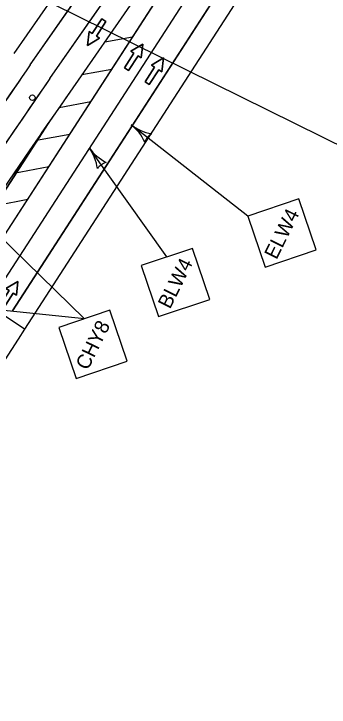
# Model space of a CAD drawing. Extents: x 14097936 to 14128734, y 8632000 to 8683104.
# Drawn here: x 14119195.8 to 14119353.7, y 8668694.3 to 8669041.8 of the extents above; entities that cross this region are included whole.
import ezdxf

# ---------------------------------------------------------------- set-up
doc = ezdxf.new("R2010")
doc.units = 0
for name, color, linetype in [('Cell', 7, 'Continuous'), ('dsn_stg_shd_prev', 7, 'Continuous'), ('dsnNonPlotable', 7, 'Continuous'), ('dsnPaintExistingChannelizingLaneWhite', 7, 'Continuous'), ('dsnPaintExistingDoubleCenterYellow', 7, 'Continuous'), ('dsnPaintPlaceBrokenLaneWhite', 7, 'Continuous'), ('dsnPaintPlaceChannelizingLaneWhite', 7, 'Continuous'), ('dsnPaintPlaceChannelizingLaneYellow', 7, 'Continuous'), ('dsnPaintPlaceEdgeLineRightWhite', 7, 'Continuous'), ('dsnPavementRmvl', 7, 'Continuous'), ('dsnShadingPaved', 7, 'Continuous'), ('dsnStdLabel', 7, 'Continuous'), ('dsnStgShadingPropPav', 7, 'Continuous'), ('Level 2', 7, 'Continuous'), ('Level 5', 7, 'Continuous')]:
    doc.layers.add(name, color=color, linetype=linetype)

msp = doc.modelspace()

# ---------------------------------------------------------------- linework, layer by layer
at = {"layer": 'Cell'}
msp.add_circle((14119205.09, 8668999.85), 1.37, dxfattribs=at)
at = {"layer": 'dsn_stg_shd_prev'}
for p, q in [((14119162.43, 8668908.54), (14119212.98, 8668986.84)), ((14119212.98, 8668986.84), (14119164.55, 8668911.89))]:
    msp.add_line(p, q, dxfattribs=at)
msp.add_arc((14121592.11, 8667345.68), 2842.95, 147.24613, 151.16499, dxfattribs=at)
at = {"layer": 'dsnNonPlotable'}
msp.add_lwpolyline([(14118047.21, 8667875.87), (14118741.94, 8669281.01), (14119647.32, 8668833.36), (14118952.59, 8667428.23)], close=True, dxfattribs=at)
at = {"layer": 'dsnPaintExistingChannelizingLaneWhite'}
for radius, end in [(1512, 159.62671), (1488, 158.15787)]:
    msp.add_arc((14120503.02, 8668359.24), radius, 147.24256, end, dxfattribs=at)
at = {"layer": 'dsnPaintExistingDoubleCenterYellow'}
msp.add_arc((14120503.02, 8668359.24), 1500, 147.24256, 159.62671, dxfattribs=at)
at = {"layer": 'dsnPaintPlaceBrokenLaneWhite'}
msp.add_line((14119527.44, 8669429.79), (14119185.09, 8668899.43), dxfattribs=at)
at = {"layer": 'dsnPaintPlaceChannelizingLaneWhite'}
msp.add_line((14119213.91, 8669009.38), (14119238.52, 8669044.85), dxfattribs=at)
msp.add_arc((14123732.96, 8665874.38), 5500, 145.2497, 146.42378, dxfattribs=at)
at = {"layer": 'dsnPaintPlaceChannelizingLaneYellow'}
for p, q in [((14119175.01, 8668905.94), (14119397.41, 8669250.48)), ((14119334.31, 8669161.88), (14119223.77, 8669002.54)), ((14119241.31, 8669027.81), (14119255.31, 8669030.35)), ((14119229.91, 8669011.38), (14119244.81, 8669014.08)), ((14119218.51, 8668994.94), (14119234.32, 8668997.83)), ((14119207.17, 8668978.47), (14119223.83, 8668981.58)), ((14119195.89, 8668961.96), (14119213.3, 8668965.27)), ((14119184.67, 8668945.4), (14119202.74, 8668948.91))]:
    msp.add_line(p, q, dxfattribs=at)
msp.add_arc((14123732.96, 8665874.38), 5488, 145.2497, 146.41498, dxfattribs=at)
at = {"layer": 'dsnPaintPlaceEdgeLineRightWhite'}
msp.add_line((14119195.17, 8668892.92), (14119537.53, 8669423.29), dxfattribs=at)
at = {"layer": 'dsnPavementRmvl'}
for radius, end in [(1512, 159.62671), (1488, 158.15787)]:
    msp.add_arc((14120503.02, 8668359.24), radius, 147.24256, end, dxfattribs=at)
at = {"layer": 'dsnShadingPaved'}
for p, q in [((14119175.01, 8668905.94), (14119517.35, 8669436.29)), ((14119213.91, 8669009.38), (14119324.45, 8669168.72)), ((14119334.31, 8669161.88), (14119223.77, 8669002.54))]:
    msp.add_line(p, q, dxfattribs=at)
msp.add_lwpolyline([(14119537.53, 8669423.29), (14119537.53, 8669423.29), (14119195.17, 8668892.92)], dxfattribs=at)
for radius in [5500, 5488]:
    msp.add_arc((14123732.96, 8665874.38), radius, 145.2497, 157.1633, dxfattribs=at)
at = {"layer": 'dsnStdLabel'}
for p, q in [((14119312.96, 8668940.41), (14119254.54, 8668986.28)), ((14119272.43, 8668919.95), (14119233.61, 8668974.6)), ((14119231.14, 8668888.99), (14119180.2, 8668938.78)), ((14119231.14, 8668888.99), (14119168.3, 8668895.51))]:
    msp.add_line(p, q, dxfattribs=at)
for points in [[(14119321.61, 8668914.84), (14119347.19, 8668923.49), (14119338.54, 8668949.06), (14119312.96, 8668940.41)], [(14119268.29, 8668890.05), (14119293.87, 8668898.7), (14119285.21, 8668924.28), (14119259.64, 8668915.63)], [(14119227, 8668859.08), (14119252.58, 8668867.74), (14119243.93, 8668893.31), (14119218.35, 8668884.66)]]:
    msp.add_lwpolyline(points, close=True, dxfattribs=at)
for centre, radius, start, end in [((14119240.37, 8668968.23), 22.95, 23.7897, 51.861), ((14119268.72, 8669004.33), 22.95, 231.8608, 259.9321), ((14119269.68, 8668974.4), 8.86, 124.1266, 159.5951), ((14119214.9, 8668961.31), 22.95, 7.3148, 35.3861), ((14119252.32, 8668987.89), 22.95, 215.3859, 243.4572), ((14119244.75, 8668958.91), 8.86, 107.6517, 143.1202)]:
    msp.add_arc(centre, radius, start, end, dxfattribs=at)
at = {"layer": 'dsnStgShadingPropPav'}
for p, q in [((14119220.45, 8669057.39), (14119195.84, 8669021.92)), ((14119204.06, 8669016.22), (14119228.66, 8669051.69))]:
    msp.add_line(p, q, dxfattribs=at)
for points in [[(14119420.33, 8669223.29), (14119201.18, 8668883.8), (14119172.86, 8668902.61), (14119172.76, 8668902.45), (14119141.1, 8668923.47)], [(14119204.06, 8669016.22), (14119228.66, 8669051.69), (14119220.45, 8669057.39), (14119306.38, 8669181.26)]]:
    msp.add_lwpolyline(points, dxfattribs=at)
for centre, radius, start, end in [((14120503.02, 8668359.24), 1512, 147.24256, 159.62671), ((14120503.02, 8668359.24), 1488, 147.24256, 158.15787), ((14123732.96, 8665874.38), 5512, 145.2497, 146.42562), ((14123732.96, 8665874.38), 5512, 145.2497, 146.41498), ((14121592.11, 8667345.68), 2842.95, 147.24613, 151.16499)]:
    msp.add_arc(centre, radius, start, end, dxfattribs=at)
at = {"layer": 'Level 2'}
for points in [[(14119241.95, 8669037.98), (14119239.85, 8669039.33), (14119235.11, 8669031.98), (14119233.53, 8669033), (14119232.77, 8669026.05), (14119238.78, 8669029.61), (14119237.21, 8669030.63)], [(14119251.18, 8669014.76), (14119253.28, 8669013.4), (14119258.04, 8669020.74), (14119259.61, 8669019.72), (14119260.39, 8669026.67), (14119254.37, 8669023.12), (14119255.94, 8669022.1)], [(14119261.49, 8669007.81), (14119263.59, 8669006.45), (14119268.35, 8669013.79), (14119269.92, 8669012.78), (14119270.7, 8669019.72), (14119264.68, 8669016.17), (14119266.25, 8669015.15)], [(14119188.65, 8668895.83), (14119190.75, 8668894.47), (14119195.51, 8668901.82), (14119197.08, 8668900.8), (14119197.86, 8668907.74), (14119191.83, 8668904.19), (14119193.41, 8668903.18)]]:
    msp.add_lwpolyline(points, close=True, dxfattribs=at)
at = {"layer": 'Level 5'}
for points in [[(14119237.21, 8669030.63), (14119238.78, 8669029.61), (14119232.77, 8669026.05), (14119233.53, 8669033), (14119235.11, 8669031.98), (14119239.85, 8669039.33), (14119241.95, 8669037.98), (14119237.21, 8669030.63)], [(14119255.94, 8669022.1), (14119254.37, 8669023.12), (14119260.39, 8669026.67), (14119259.61, 8669019.72), (14119258.04, 8669020.74), (14119253.28, 8669013.4), (14119251.18, 8669014.76), (14119255.94, 8669022.1)], [(14119266.25, 8669015.15), (14119264.68, 8669016.17), (14119270.7, 8669019.72), (14119269.92, 8669012.78), (14119268.35, 8669013.79), (14119263.59, 8669006.45), (14119261.49, 8669007.81), (14119266.25, 8669015.15)], [(14119193.41, 8668903.18), (14119191.83, 8668904.19), (14119197.86, 8668907.74), (14119197.08, 8668900.8), (14119195.51, 8668901.82), (14119190.75, 8668894.47), (14119188.65, 8668895.83), (14119193.41, 8668903.18)]]:
    msp.add_lwpolyline(points, dxfattribs=at)

# ---------------------------------------------------------------- texts
at = {"layer": 'dsnStdLabel'}
for s, p in [('ELW4', (14119327.34, 8668918.3)), ('BLW4', (14119274.02, 8668893.51)), ('CHY8', (14119232.85, 8668862.77))]:
    msp.add_text(s, height=7.2, rotation=63.6912, dxfattribs=at).set_placement(p)

doc.saveas('drawing.dxf')
